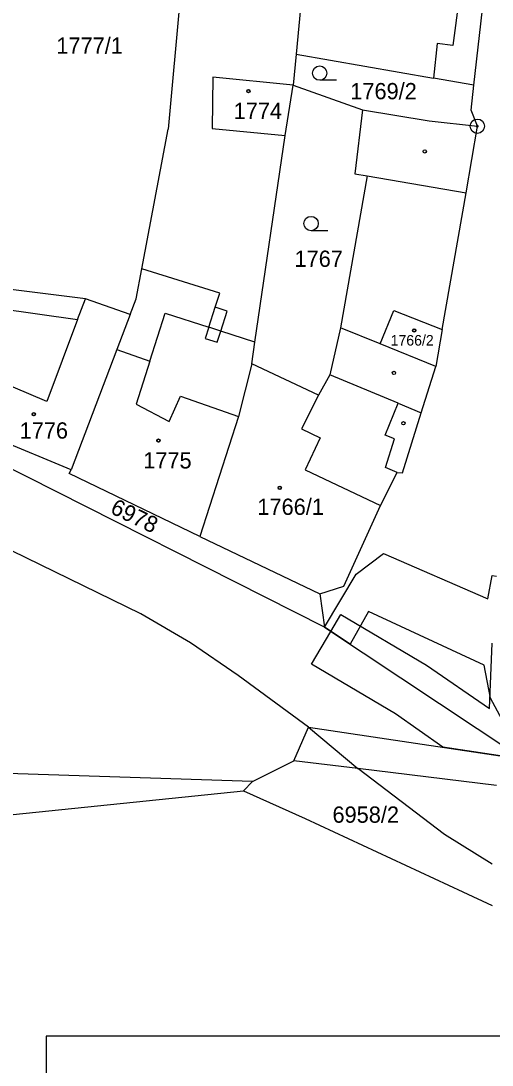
# Model space of a CAD drawing. Extents: x -593183 to -588034, y -1130415 to -1124994.
# Drawn here: x -590317.4 to -590268.1, y -1129347.3 to -1129238.2 of the extents above; entities that cross this region are included whole.
import ezdxf

# ---------------------------------------------------------------- set-up
doc = ezdxf.new("R2010")
doc.units = 0
for name, color, linetype in [('Vrstva 1', 7, 'Continuous'), ('Vrstva 18', 7, 'Continuous'), ('Vrstva 19', 7, 'Continuous'), ('Vrstva 24', 7, 'Continuous'), ('Vrstva 25', 7, 'Continuous'), ('Vrstva 27', 7, 'Continuous'), ('Vrstva 4', 7, 'Continuous')]:
    doc.layers.add(name, color=color, linetype=linetype)

msp = doc.modelspace()

# ---------------------------------------------------------------- linework, layer by layer
at = {"layer": 'Vrstva 1'}
for p, q in [((-590270.03, -1129244.97), (-590261.36, -1129168.64)), ((-590285.27, -1129206.55), (-590288.61, -1129241.71)), ((-590299.05, -1129217), (-590302, -1129249.55)), ((-590271.46, -1129234.86), (-590272.24, -1129240.82)), ((-590273.88, -1129240.61), (-590274.25, -1129244.23)), ((-590272.24, -1129240.82), (-590273.88, -1129240.61)), ((-590288.61, -1129241.71), (-590288.92, -1129244.98)), ((-590288.61, -1129241.71), (-590274.25, -1129244.23)), ((-590297.34, -1129244.14), (-590297.4, -1129249.48)), ((-590288.92, -1129244.98), (-590297.34, -1129244.14)), ((-590270.03, -1129244.97), (-590274.25, -1129244.23)), ((-590289.78, -1129250.23), (-590288.92, -1129244.98)), ((-590288.92, -1129244.98), (-590281.69, -1129247.55)), ((-590270.33, -1129247.58), (-590270.03, -1129244.97)), ((-590281.69, -1129247.55), (-590282.48, -1129254.22)), ((-590281.69, -1129247.55), (-590274.71, -1129248.7)), ((-590269.68, -1129249.25), (-590270.33, -1129247.58)), ((-590274.71, -1129248.7), (-590269.68, -1129249.25)), ((-590304.74, -1129264.15), (-590302, -1129249.55)), ((-590297.4, -1129249.48), (-590289.78, -1129250.23)), ((-590270.84, -1129256.23), (-590269.68, -1129249.25)), ((-590292.93, -1129271.82), (-590289.78, -1129250.23)), ((-590281.19, -1129254.44), (-590283.99, -1129270.31)), ((-590282.48, -1129254.22), (-590281.19, -1129254.44)), ((-590273.35, -1129270.5), (-590270.84, -1129256.23)), ((-590305.33, -1129267.29), (-590304.74, -1129264.15)), ((-590296.6, -1129266.7), (-590304.74, -1129264.15)), ((-590310.65, -1129267.29), (-590325.46, -1129265.44)), ((-590305.95, -1129268.92), (-590310.65, -1129267.29)), ((-590305.95, -1129268.92), (-590305.33, -1129267.29)), ((-590297.08, -1129268.17), (-590296.6, -1129266.7)), ((-590295.82, -1129268.58), (-590297.08, -1129268.17)), ((-590305.95, -1129268.92), (-590307.35, -1129272.59)), ((-590296.5, -1129270.67), (-590295.82, -1129268.58)), ((-590279.82, -1129272), (-590278.41, -1129268.52)), ((-590278.41, -1129268.52), (-590273.35, -1129270.5)), ((-590283.99, -1129270.31), (-590285.11, -1129275.23)), ((-590273.35, -1129270.5), (-590274.02, -1129274.35)), ((-590292.93, -1129271.82), (-590296.5, -1129270.67)), ((-590307.35, -1129272.59), (-590312.15, -1129285.15)), ((-590293.26, -1129274.08), (-590292.93, -1129271.82)), ((-590274.02, -1129274.35), (-590279.82, -1129272)), ((-590293.26, -1129274.08), (-590294.64, -1129279.57)), ((-590286.29, -1129277.35), (-590293.26, -1129274.08)), ((-590275.55, -1129279.2), (-590274.02, -1129274.35)), ((-590285.11, -1129275.23), (-590286.29, -1129277.35)), ((-590312.15, -1129285.15), (-590329.11, -1129278.11)), ((-590277.52, -1129285.48), (-590275.55, -1129279.2)), ((-590285.65, -1129301.59), (-590329.44, -1129279.46)), ((-590294.64, -1129279.57), (-590298.67, -1129292.1)), ((-590312.35, -1129285.54), (-590312.15, -1129285.15)), ((-590298.67, -1129292.1), (-590312.35, -1129285.54)), ((-590279.8, -1129288.88), (-590278.05, -1129285.42)), ((-590278.05, -1129285.42), (-590277.52, -1129285.48)), ((-590304.84, -1129300.21), (-590331.92, -1129286.99)), ((-590283.64, -1129297.29), (-590279.8, -1129288.88)), ((-590298.67, -1129292.1), (-590286.13, -1129298.11)), ((-590286.13, -1129298.11), (-590283.64, -1129297.29)), ((-590286.13, -1129298.11), (-590285.65, -1129301.59)), ((-590299.65, -1129303.21), (-590304.84, -1129300.21)), ((-590285.65, -1129301.59), (-590264.88, -1129315.4)), ((-590294.67, -1129306.64), (-590299.65, -1129303.21)), ((-590287.34, -1129312.04), (-590294.67, -1129306.64)), ((-590288.87, -1129315.56), (-590287.34, -1129312.04)), ((-590287.34, -1129312.04), (-590264.88, -1129315.4)), ((-590293.17, -1129317.71), (-590342.94, -1129316.1)), ((-590293.17, -1129317.71), (-590288.87, -1129315.56)), ((-590282.17, -1129316.37), (-590288.87, -1129315.56)), ((-590267.69, -1129318.12), (-590282.17, -1129316.37)), ((-590273.12, -1129323.24), (-590282.17, -1129316.37)), ((-590294.12, -1129318.7), (-590293.17, -1129317.71)), ((-590319.56, -1129321.29), (-590294.12, -1129318.7)), ((-590294.12, -1129318.7), (-590287.67, -1129321.57)), ((-590287.67, -1129321.57), (-590271.18, -1129329.22)), ((-590268.13, -1129326.34), (-590273.12, -1129323.24)), ((-590271.18, -1129329.22), (-590268.12, -1129330.67)), ((-589684.75, -1129344.33), (-590314.75, -1129344.33)), ((-590314.75, -1129344.33), (-590314.75, -1129641.33))]:
    msp.add_line(p, q, dxfattribs=at)
at = {"layer": 'Vrstva 24'}
for radius in [0.75, 0.0903]:
    msp.add_circle((-590269.68, -1129249.25), radius, dxfattribs=at)
at = {"layer": 'Vrstva 25'}
for p, q in [((-590284.41, -1129244.46), (-590286.16, -1129244.46)), ((-590285.31, -1129260.17), (-590287.06, -1129260.17))]:
    msp.add_line(p, q, dxfattribs=at)
for centre, radius in [((-590286.16, -1129243.71), 0.75), ((-590293.61, -1129245.59), 0.175), ((-590293.61, -1129245.59), 0.15), ((-590275.18, -1129251.88), 0.175), ((-590287.06, -1129259.42), 0.75), ((-590276.28, -1129270.59), 0.175), ((-590276.28, -1129270.59), 0.15), ((-590278.4, -1129275.02), 0.175), ((-590316.05, -1129279.35), 0.175), ((-590316.05, -1129279.35), 0.15), ((-590277.41, -1129280.29), 0.175), ((-590303.01, -1129282.1), 0.175), ((-590303.01, -1129282.1), 0.15), ((-590290.34, -1129287.03), 0.175), ((-590290.34, -1129287.03), 0.15)]:
    msp.add_circle(centre, radius, dxfattribs=at)
at = {"layer": 'Vrstva 27'}
for p, q in [((-590282.34, -1129296.06), (-590279.5, -1129293.9)), ((-590279.5, -1129293.9), (-590268.57, -1129298.62)), ((-590285.65, -1129301.59), (-590282.34, -1129296.06)), ((-590268.57, -1129298.62), (-590268.14, -1129296.18)), ((-590268.14, -1129296.18), (-590267.69, -1129296.26)), ((-590281.07, -1129299.95), (-590282.98, -1129303.36)), ((-590268.95, -1129305.55), (-590281.07, -1129299.95)), ((-590284.99, -1129302.03), (-590283.96, -1129300.28)), ((-590283.96, -1129300.28), (-590275.01, -1129305.57)), ((-590287.01, -1129305.45), (-590284.99, -1129302.03)), ((-590282.98, -1129303.36), (-590285.65, -1129301.59)), ((-590268.4, -1129310.1), (-590268.13, -1129303.27)), ((-590278.23, -1129310.63), (-590287.01, -1129305.45)), ((-590275.01, -1129305.57), (-590268.4, -1129310.1)), ((-590268.3, -1129309.01), (-590268.95, -1129305.55)), ((-590264.88, -1129315.4), (-590268.3, -1129309.01)), ((-590273.29, -1129314.14), (-590278.23, -1129310.63)), ((-590264.88, -1129315.4), (-590273.29, -1129314.14))]:
    msp.add_line(p, q, dxfattribs=at)
at = {"layer": 'Vrstva 4'}
for p, q in [((-590281.19, -1129254.44), (-590270.84, -1129256.23)), ((-590311.46, -1129269.46), (-590310.65, -1129267.29)), ((-590325.24, -1129267.47), (-590311.46, -1129269.46)), ((-590297.75, -1129270.26), (-590297.08, -1129268.17)), ((-590311.46, -1129269.46), (-590314.66, -1129278.02)), ((-590303.91, -1129273.8), (-590302.32, -1129268.78)), ((-590302.32, -1129268.78), (-590297.75, -1129270.26)), ((-590297.75, -1129270.26), (-590298.13, -1129271.42)), ((-590296.5, -1129270.67), (-590297.75, -1129270.26)), ((-590279.82, -1129272), (-590283.99, -1129270.31)), ((-590298.13, -1129271.42), (-590296.87, -1129271.83)), ((-590296.87, -1129271.83), (-590296.5, -1129270.67)), ((-590307.35, -1129272.59), (-590303.91, -1129273.8)), ((-590314.66, -1129278.02), (-590326.62, -1129272.96)), ((-590303.91, -1129273.8), (-590305.33, -1129278.3)), ((-590277.94, -1129278.17), (-590285.11, -1129275.23)), ((-590301.9, -1129280.09), (-590300.7, -1129277.45)), ((-590300.7, -1129277.45), (-590294.64, -1129279.57)), ((-590286.29, -1129277.35), (-590288.07, -1129280.88)), ((-590279.32, -1129281.53), (-590277.94, -1129278.17)), ((-590277.94, -1129278.17), (-590275.55, -1129279.2)), ((-590305.33, -1129278.3), (-590301.9, -1129280.09)), ((-590288.07, -1129280.88), (-590286.11, -1129281.8)), ((-590286.11, -1129281.8), (-590287.69, -1129285.14)), ((-590278.33, -1129281.93), (-590279.32, -1129281.53)), ((-590279.29, -1129284.9), (-590278.33, -1129281.93)), ((-590287.69, -1129285.14), (-590279.8, -1129288.88)), ((-590278.05, -1129285.42), (-590279.29, -1129284.9)), ((-590287.34, -1129312.04), (-590282.17, -1129316.37))]:
    msp.add_line(p, q, dxfattribs=at)

# ---------------------------------------------------------------- texts
at = {"layer": 'Vrstva 18'}
for s, p in [('1777/1', (-590313.68, -1129241.68)), ('1769/2', (-590282.96, -1129246.44)), ('1767', (-590288.79, -1129263.95)), ('6958/2', (-590284.82, -1129322.02))]:
    msp.add_text(s, height=1.7, dxfattribs=at).set_placement(p)
msp.add_text('6978', height=1.7, rotation=334.2901, dxfattribs=at).set_placement((-590308.15, -1129289.63))
at = {"layer": 'Vrstva 19'}
for s, height, p in [('1774', 1.7, (-590295.15, -1129248.5)), ('1766/2', 1.1, (-590278.74, -1129272.17)), ('1776', 1.7, (-590317.52, -1129281.89)), ('1775', 1.7, (-590304.6, -1129285.01)), ('1766/1', 1.7, (-590292.67, -1129289.86))]:
    msp.add_text(s, height=height, dxfattribs=at).set_placement(p)

doc.saveas('drawing.dxf')
